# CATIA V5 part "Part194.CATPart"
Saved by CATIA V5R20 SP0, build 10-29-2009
Part number: FA 168700-2 comprimido
Revision: ANY
Definition: UNKNOWN
Nomenclature: FA 168700-2 comprimido
Source: Unknown
Bounding box of the stored display mesh (mm): x -2.8 to 2.8, y 0 to 4.04, z -2.8 to 2.8
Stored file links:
  C:\Users\Utente\Desktop\IO LAVORO\3D X SITO CF\CUMSA\3D files FA\FA 168710-20\Part194.CATPart
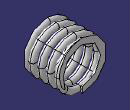
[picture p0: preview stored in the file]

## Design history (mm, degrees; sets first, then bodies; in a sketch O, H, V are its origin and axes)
Body1 "Cortar-Extruir1" (main body)
  Solid1: solid without history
